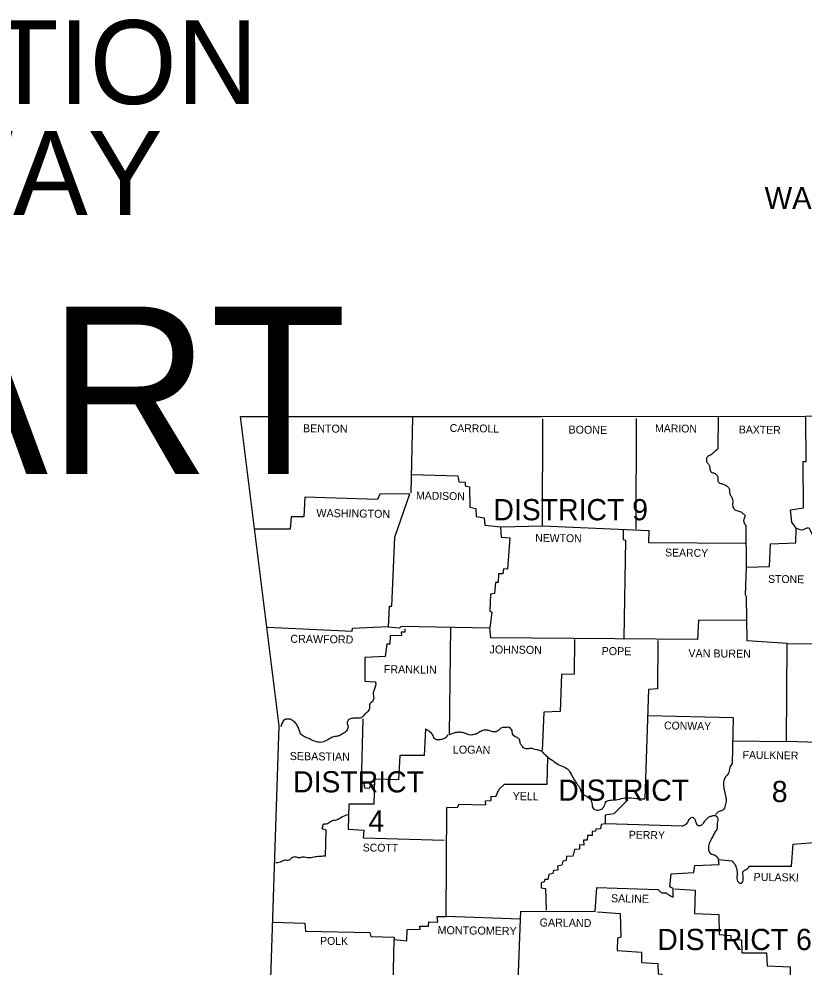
# Model space of a CAD drawing. Extents: x 1196286 to 1268366, y 2040822 to 2082115.
# Drawn here: x 1243666 to 1252098, y 2071784 to 2081971 of the extents above; entities that cross this region are included whole.
import ezdxf

# ---------------------------------------------------------------- set-up
doc = ezdxf.new("R2010")
doc.units = 0
for name, color, linetype in [('21', 7, 'Continuous'), ('60', 7, 'Continuous'), ('Default', 7, 'Continuous'), ('Level 8', 7, 'Continuous')]:
    doc.layers.add(name, color=color, linetype=linetype)

msp = doc.modelspace()

# ---------------------------------------------------------------- linework, layer by layer
at = {"layer": '21'}
msp.add_lwpolyline([(1249052, 2072298), (1248256, 2072328)], dxfattribs=at)
at = {"layer": 'Level 8'}
for points in [[(1246046, 2077700), (1249280, 2077698), (1252118, 2077704), (1255466, 2077756), (1257018, 2077792)], [(1246280, 2068950), (1246460, 2074376), (1246046, 2077700)], [(1247892, 2077688), (1247874, 2076878)], [(1247888, 2077076), (1248380, 2077060), (1248392, 2076996), (1248460, 2076994), (1248458, 2076954), (1248506, 2076942), (1248510, 2076724), (1248572, 2076710), (1248576, 2076624), (1248664, 2076612), (1248668, 2076532), (1248842, 2076514), (1249290, 2076524), (1249294, 2077674)], [(1250296, 2077678), (1250290, 2076490)], [(1251176, 2077692), (1251172, 2077350)], [(1251512, 2072866), (1251962, 2072868), (1251982, 2073104), (1252250, 2073124), (1252250, 2074196), (1251910, 2074206), (1251916, 2075260), (1251488, 2075288), (1251482, 2075760), (1251468, 2075784), (1251480, 2076080), (1251728, 2076088), (1251738, 2076332), (1252010, 2076342), (1252014, 2076500), (1251966, 2076562), (1251954, 2076696), (1252094, 2076716), (1252088, 2077214), (1252122, 2077216), (1252118, 2077692)], [(1248734, 2075320), (1248724, 2075426), (1247770, 2075444), (1247752, 2075426), (1247634, 2075436), (1247646, 2075660), (1247670, 2075662), (1247702, 2076404), (1247864, 2076868), (1247542, 2076866), (1247518, 2076806), (1246738, 2076834), (1246726, 2076620), (1246588, 2076620), (1246578, 2076488), (1246204, 2076490)], [(1248838, 2076510), (1248846, 2076402), (1248938, 2076396), (1248914, 2076060), (1248872, 2076062), (1248864, 2076008), (1248816, 2076008), (1248814, 2075916), (1248784, 2075914), (1248774, 2075796), (1248730, 2075790), (1248724, 2075610), (1248744, 2075596), (1248724, 2075426)], [(1249290, 2076524), (1250430, 2076476), (1250428, 2076346), (1251474, 2076338)], [(1250156, 2076482), (1250154, 2076378), (1250180, 2076372), (1250164, 2075316)], [(1251480, 2076080), (1251478, 2076530)], [(1251480, 2075506), (1250964, 2075512), (1250954, 2075302), (1248734, 2075320)], [(1246336, 2075434), (1247246, 2075392), (1247250, 2075424), (1247630, 2075442)], [(1247810, 2075418), (1247810, 2075382), (1247772, 2075382), (1247774, 2075346), (1247652, 2075344), (1247650, 2075254), (1247616, 2075254), (1247598, 2075120), (1247382, 2075110), (1247380, 2074856), (1247496, 2074848)], [(1248290, 2074280), (1248304, 2075434)], [(1249632, 2075304), (1249630, 2074930), (1249492, 2074928), (1249480, 2074530), (1249304, 2074524), (1249284, 2074112)], [(1250528, 2075294), (1250524, 2074774), (1250428, 2074766), (1250390, 2073590)], [(1251916, 2075260), (1252944, 2075254), (1253032, 2075296), (1253026, 2074514), (1252966, 2074488), (1252912, 2074442), (1252894, 2074424), (1252892, 2074200), (1252238, 2074200)], [(1247360, 2074452), (1247340, 2073764), (1247370, 2073756), (1247376, 2073708), (1247436, 2073704), (1247442, 2073738), (1247490, 2073746)], [(1250424, 2074488), (1251338, 2074466), (1251326, 2073972)], [(1248032, 2074344), (1248018, 2074058), (1247758, 2074056), (1247744, 2073796), (1247486, 2073802), (1247478, 2073534), (1247208, 2073532), (1247200, 2073264), (1247370, 2073254), (1247364, 2073172), (1248232, 2073148)], [(1251328, 2074214), (1251910, 2074206)], [(1247674, 2071094), (1247696, 2072078), (1247832, 2072066), (1247834, 2072188), (1247974, 2072192), (1247972, 2072224), (1248066, 2072224), (1248068, 2072268), (1248164, 2072266), (1248156, 2072326), (1248256, 2072328), (1248260, 2073498), (1248380, 2073502), (1248390, 2073534), (1248680, 2073526), (1248678, 2073568), (1248736, 2073574), (1248738, 2073620), (1248788, 2073616), (1248822, 2073696), (1248882, 2073748), (1249338, 2073750), (1249346, 2074038)], [(1250204, 2073582), (1250132, 2073504), (1250054, 2073430), (1249964, 2073416), (1249964, 2073322), (1249920, 2073316), (1249912, 2073268), (1249862, 2073264), (1249858, 2073242), (1249824, 2073240), (1249822, 2073198), (1249774, 2073196), (1249770, 2073148), (1249730, 2073148), (1249732, 2073092), (1249688, 2073096), (1249686, 2073052), (1249632, 2073048), (1249616, 2072976), (1249548, 2072970), (1249542, 2072930), (1249506, 2072920), (1249496, 2072878), (1249450, 2072868), (1249454, 2072826), (1249408, 2072822), (1249400, 2072790), (1249358, 2072778), (1249348, 2072724), (1249316, 2072726), (1249306, 2072698), (1249276, 2072688), (1249274, 2072634), (1249320, 2072626), (1249328, 2072394)], [(1246958, 2072974), (1246964, 2073256), (1246924, 2073268), (1246936, 2073322)], [(1250790, 2073298), (1249966, 2073324)], [(1250692, 2072534), (1250692, 2072626), (1250656, 2072644), (1250670, 2072784), (1250916, 2072798), (1250924, 2072876), (1251186, 2072886), (1251180, 2072940), (1251324, 2072924)], [(1251952, 2072870), (1251962, 2072880)], [(1249052, 2072298), (1249056, 2072384), (1249856, 2072380), (1249874, 2072638), (1250528, 2072618)], [(1250706, 2072624), (1250930, 2072610), (1250922, 2072360), (1251184, 2072350), (1251188, 2072132), (1251312, 2072122), (1251312, 2072084), (1251428, 2072076), (1251432, 2071936), (1251696, 2071936), (1251704, 2071798), (1251948, 2071786), (1251946, 2071526)], [(1249880, 2072376), (1250122, 2072358), (1250130, 2072106), (1250096, 2072094), (1250092, 2071960), (1250354, 2071942), (1250354, 2071832), (1250528, 2071822), (1250530, 2071712), (1250572, 2071706), (1250570, 2071558)], [(1246390, 2072266), (1246736, 2072254), (1246744, 2072170), (1247436, 2072156), (1247444, 2072112), (1247696, 2072104), (1247694, 2072066)], [(1249006, 2071052), (1249052, 2072298)]]:
    msp.add_lwpolyline(points, dxfattribs=at)
for points in [[(1251172, 2077350), (1251136, 2077320), (1251104, 2077292), (1251056, 2077258), (1251050, 2077226), (1251066, 2077194), (1251082, 2077168), (1251088, 2077132), (1251102, 2077102), (1251136, 2077090), (1251164, 2077064), (1251174, 2077028), (1251178, 2076994), (1251210, 2076978), (1251246, 2076966), (1251280, 2076942), (1251296, 2076912), (1251300, 2076874), (1251314, 2076844), (1251330, 2076808), (1251334, 2076778), (1251330, 2076748), (1251338, 2076720), (1251364, 2076692), (1251410, 2076678), (1251442, 2076658), (1251464, 2076630), (1251450, 2076596), (1251452, 2076566), (1251470, 2076530)], [(1252014, 2076500), (1252094, 2076486), (1252142, 2076504), (1252176, 2076452), (1252194, 2076412), (1252224, 2076354), (1252272, 2076336), (1252308, 2076304), (1252308, 2076270), (1252276, 2076238), (1252252, 2076206), (1252260, 2076168), (1252268, 2076116), (1252268, 2076066), (1252256, 2076020), (1252246, 2075978), (1252256, 2075942), (1252294, 2075948), (1252334, 2075978), (1252376, 2075978), (1252416, 2075956), (1252458, 2075918), (1252500, 2075926), (1252534, 2075936), (1252582, 2075950), (1252616, 2075932), (1252646, 2075908), (1252682, 2075870), (1252716, 2075846), (1252760, 2075824), (1252814, 2075810), (1252864, 2075776), (1252872, 2075718), (1252870, 2075668), (1252866, 2075606), (1252862, 2075538), (1252868, 2075472), (1252890, 2075428), (1252918, 2075376), (1252926, 2075328), (1252924, 2075252)], [(1247496, 2074848), (1247496, 2074806), (1247480, 2074762), (1247470, 2074724), (1247476, 2074674), (1247458, 2074634), (1247432, 2074602), (1247432, 2074562), (1247402, 2074520), (1247370, 2074488), (1247342, 2074462), (1247292, 2074458), (1247250, 2074456), (1247208, 2074442), (1247192, 2074412), (1247200, 2074366), (1247184, 2074322), (1247142, 2074288), (1247096, 2074266), (1247048, 2074258), (1246982, 2074226), (1246922, 2074200), (1246858, 2074204), (1246798, 2074230), (1246744, 2074254), (1246702, 2074278), (1246668, 2074352), (1246646, 2074392), (1246608, 2074432), (1246562, 2074448), (1246524, 2074444), (1246478, 2074366)], [(1248032, 2074344), (1248076, 2074316), (1248110, 2074270), (1248140, 2074232), (1248190, 2074230), (1248230, 2074238), (1248276, 2074278)], [(1249346, 2074038), (1249308, 2074074), (1249268, 2074108), (1249224, 2074118), (1249156, 2074132), (1249112, 2074128), (1249086, 2074140), (1249068, 2074160), (1249050, 2074190), (1249040, 2074232), (1249006, 2074254), (1248968, 2074288), (1248962, 2074324), (1248932, 2074358), (1248890, 2074358), (1248842, 2074350), (1248814, 2074324), (1248766, 2074310), (1248722, 2074322), (1248680, 2074330), (1248636, 2074322), (1248596, 2074296), (1248556, 2074282), (1248502, 2074278), (1248452, 2074298), (1248404, 2074306), (1248356, 2074302), (1248290, 2074280)], [(1249346, 2074038), (1249416, 2073990), (1249482, 2073948), (1249550, 2073918), (1249588, 2073874), (1249622, 2073806), (1249650, 2073764), (1249686, 2073712), (1249712, 2073654), (1249754, 2073622), (1249798, 2073594), (1249820, 2073544), (1249830, 2073494), (1249878, 2073470), (1249924, 2073480), (1249950, 2073510), (1249974, 2073562), (1250028, 2073578), (1250098, 2073584), (1250178, 2073602), (1250266, 2073598), (1250390, 2073590)], [(1251326, 2073972), (1251300, 2073926), (1251288, 2073866), (1251256, 2073828), (1251236, 2073784), (1251234, 2073726), (1251244, 2073674), (1251254, 2073624), (1251262, 2073578), (1251252, 2073520), (1251226, 2073470), (1251186, 2073456), (1251148, 2073422)], [(1246936, 2073322), (1246980, 2073326), (1247022, 2073354), (1247078, 2073366), (1247134, 2073396), (1247204, 2073428)], [(1250790, 2073298), (1250840, 2073326), (1250866, 2073368), (1250898, 2073394), (1250930, 2073358), (1250958, 2073306), (1250988, 2073306), (1251026, 2073342), (1251050, 2073374), (1251080, 2073398), (1251112, 2073408), (1251146, 2073412), (1251172, 2073374), (1251164, 2073314), (1251164, 2073274), (1251142, 2073232), (1251118, 2073188), (1251092, 2073138), (1251072, 2073084), (1251076, 2073032), (1251104, 2072998), (1251136, 2072988), (1251180, 2072944)], [(1246958, 2072974), (1246900, 2072972), (1246834, 2072964), (1246774, 2072956), (1246720, 2072966), (1246670, 2072958), (1246636, 2072966), (1246594, 2072956), (1246570, 2072932), (1246520, 2072932), (1246484, 2072916), (1246426, 2072902)], [(1251324, 2072924), (1251358, 2072880), (1251378, 2072820), (1251378, 2072752), (1251394, 2072696), (1251426, 2072684), (1251446, 2072732), (1251442, 2072780), (1251442, 2072808), (1251476, 2072832), (1251512, 2072866)], [(1250528, 2072618), (1250552, 2072596), (1250578, 2072580), (1250610, 2072582), (1250640, 2072564), (1250692, 2072534)]]:
    msp.add_spline(points, degree=3, dxfattribs=at)

# ---------------------------------------------------------------- texts
at = {"layer": '21'}
for s, p in [('DISTRICT 9', (1248762, 2076584)), ('DISTRICT', (1246610, 2073660)), ('DISTRICT', (1249458, 2073570)), ('8', (1251752, 2073556)), ('4', (1247420, 2073240)), ('DISTRICT 6', (1250522, 2071966))]:
    msp.add_text(s, height=228, dxfattribs=at).set_placement(p)
at = {"layer": '60'}
for s, p in [('ARKANSAS DEPARTMENT OF TRANSPORTATION', (1217611, 2081057)), ('CONSTRUCTION PLANS FOR STATE HIGHWAY', (1218060, 2079865))]:
    msp.add_text(s, height=900, dxfattribs=at).set_placement(p)
for s, height, rotation, p in [('BENTON', 86, 359.2527, (1246716, 2077530)), ('CARROLL', 84, 359.1481, (1248292, 2077534)), ('BOONE', 86, 359.4001, (1249568, 2077516)), ('MARION', 84, 359.1854, (1250498, 2077532)), ('BAXTER', 84, 359.2559, (1251398, 2077518)), ('MADISON', 84, 359.0906, (1247930, 2076808)), ('WASHINGTON', 86, 359.232, (1246860, 2076620)), ('NEWTON', 84, 359.2717, (1249210, 2076354)), ('SEARCY', 84, 359.2527, (1250606, 2076196)), ('STONE', 84, 359.4001, (1251712, 2075912)), ('CRAWFORD', 86, 359.2771, (1246580, 2075268)), ('JOHNSON', 86, 359.3514, (1248720, 2075154)), ('POPE', 86, 359.6155, (1249924, 2075136)), ('VAN BUREN', 86, 359.3508, (1250856, 2075114)), ('FRANKLIN', 86, 359.1815, (1247584, 2074942)), ('CONWAY', 84, 359.0371, (1250594, 2074338)), ('LOGAN', 86, 359.3969, (1248326, 2074078)), ('SEBASTIAN', 86, 359.2816, (1246574, 2074008)), ('FAULKNER', 84, 359.2486, (1251438, 2074022)), ('YELL', 86, 359.1987, (1248968, 2073578)), ('PERRY', 84, 359.0858, (1250216, 2073164)), ('SCOTT', 84, 359.4063, (1247358, 2073026)), ('PULASKI', 86, 359.053, (1251556, 2072710)), ('SALINE', 86, 359.1491, (1250024, 2072480)), ('GARLAND', 86, 359.3658, (1249258, 2072220)), ('MONTGOMERY', 86, 359.2944, (1248162, 2072138)), ('POLK', 84, 359.2152, (1246900, 2072024))]:
    msp.add_text(s, height=height, rotation=rotation, dxfattribs=at).set_placement(p)
at = {"layer": 'Default'}
msp.add_text('WABBASEKA - STUTTGART', height=1800, dxfattribs=at).set_placement((1215491, 2077081))
at = {"layer": 'Level 8'}
msp.add_text('WABBASEKA - STUTTGART (PASSING LANES) (S)', height=234.48, dxfattribs=at).set_placement((1251675, 2079930))

doc.saveas('drawing.dxf')
